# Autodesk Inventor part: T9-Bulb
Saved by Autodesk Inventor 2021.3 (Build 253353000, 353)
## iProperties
Created: 2022-08
Part Number: T9-Bulb
Material: Generic
Document SubType Name: Modeling
Designer: Administrator
Density: 1 g/cm^3
Appearance: Default
Title: T9-Bulb
Author: Administrator
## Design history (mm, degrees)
feature "T9-Bulb"
body "Solid1"
